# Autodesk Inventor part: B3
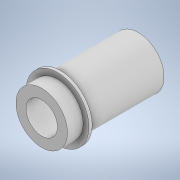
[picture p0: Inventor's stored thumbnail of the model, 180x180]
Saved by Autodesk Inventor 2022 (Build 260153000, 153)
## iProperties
Created: 2024-12
Part Number: B3
Material: 一般
Document SubType Name: Modeling
Designer: jsat7
Density: 1 g/cm^3
Appearance: 既定
Author: jsat7
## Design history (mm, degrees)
sketch "スケッチ1"
  geometry: C1 r 2.45 at (0, 0); 1 further point
  constraints: 1 centre point, 1 coincident
  dimensions: "d0" = 4.9 diameter of C1
extrude "押し出し1" new body sketch "スケッチ1" distance "d1" = 1.5; taper "d2" = 0 deg
sketch "スケッチ2"
  geometry: C1 r 3 at (0, 0); 1 further point
  constraints: 1 centre point, 1 coincident
  dimensions: "d3" = 6 diameter of C1
extrude "押し出し2" join sketch "スケッチ2" distance "d4" = 0.3; taper "d5" = 0 deg
sketch "スケッチ3"
  geometry: C1 r 2.45 at (0, 0); 1 further point
  constraints: 1 centre point, 1 coincident
  dimensions: "d6" = 4.9 diameter of C1
extrude "押し出し3" join sketch "スケッチ3" distance "d7" = 7.4; taper "d8" = 0 deg
sketch "スケッチ4"
  geometry: C1 r 1.5 at (0, 0); 1 further point
  constraints: 1 centre point, 1 coincident
  dimensions: "d9" = 3 diameter of C1
extrude "押し出し4" cut sketch "スケッチ4" distance "d10" = 10; taper "d11" = 0 deg
node "ソリッド1"
